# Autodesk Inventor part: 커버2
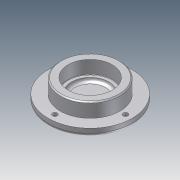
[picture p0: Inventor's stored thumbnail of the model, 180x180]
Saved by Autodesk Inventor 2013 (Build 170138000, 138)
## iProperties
Company: 한국ATC센터
Created: 2014-10
Part Number: 커버2
Document SubType Name: Modeling
Designer: KYOUNG IL JANG
Density: 1 g/cm^3
Mass: 44.7286 g
Surface Area: 161.165 cm^2
Volume: 44.7286 cm^3
Material: 일반
Author: KYOUNG IL JANG
Revision Number: 1
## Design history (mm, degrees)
sketch "스케치1"
  geometry: C1 r 38 at (0, 0); 1 further point
  constraints: 1 centre point, 1 coincident
  dimensions: "d0" = 76 diameter of C1
extrude "돌출1" new body sketch "스케치1" distance "d1" = 7; taper "d2" = 0 deg
sketch "스케치2"
  geometry: C1 r 27 at (0, 0); 1 further point
  constraints: 1 centre point, 1 coincident
  dimensions: "d3" = 54 diameter of C1
extrude "돌출2" join sketch "스케치2" distance "d4" = 13; taper "d5" = 0 deg
hole "구멍2" diameter "d20" = 34; stored, may be unused: countersink angle "d24" = 90 deg, drill point angle "d26" = 0 deg; dims "d18" = 10, "d19" = 10, "d21" = 6, "d22" = 40, "d23" = 12, "d25" = 3
fillet "모깎기2" dims "d34" = 3
fillet "모깎기1" dims "d27" = 0.3
chamfer "모따기1" distance "d28" = 1; stored, may be unused: second distance "d29" = 2, angle "d30" = 45 deg
sketch "스케치4" dims "d35" = 64
  geometry: 3 further points
  constraints: 2 horizontal alignment, 1 coincident, 2 other
hole "구멍3" sketch "스케치4" at (32, 0) diameter "d36" = 4.5; stored, may be unused: countersink angle "d40" = 90 deg, drill point angle "d42" = 118 deg; dims "d37" = 6, "d38" = 8, "d39" = 4.4, "d41" = 13
node "솔리드1"
pattern_circular "원형 패턴1" dims angle "d44" = 360 deg
